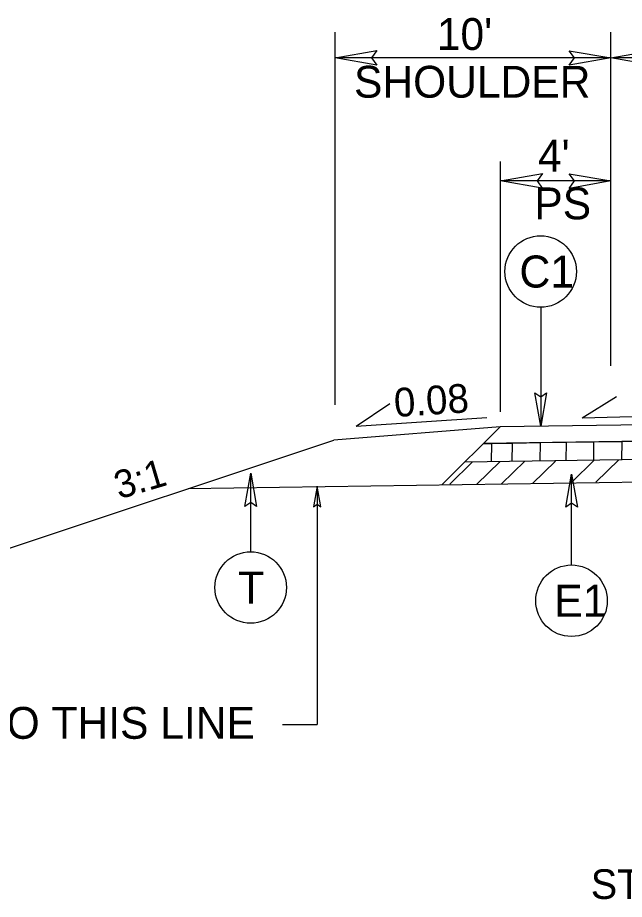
# Model space of a CAD drawing. Extents: x 2176024 to 2177225, y 75947 to 76635.
# Drawn here: x 2176290.4 to 2176312.4, y 76460.33 to 76492.28 of the extents above; entities that cross this region are included whole.
import ezdxf

# ---------------------------------------------------------------- set-up
doc = ezdxf.new("R2010")
doc.units = 0
for name, color, linetype in [('Old_Level_1', 7, 'Continuous'), ('Old_Level_11', 7, 'Continuous'), ('Prop Dimension', 7, 'Continuous'), ('Typical Curb CELL', 7, 'Continuous'), ('Typical Pavement Slope CELL', 7, 'Continuous'), ('Typical Pavement Slope Information CELL', 7, 'Continuous'), ('Typical Shoulder Slope CELL', 7, 'Continuous'), ('Typical Slope Point Local CELL', 7, 'Continuous'), ('Typical Terminator CELL', 7, 'Continuous'), ('Typical Text General CELL', 7, 'Continuous'), ('Typical Text Label CELL', 7, 'Continuous')]:
    doc.layers.add(name, color=color, linetype=linetype)

msp = doc.modelspace()

# ---------------------------------------------------------------- linework, layer by layer
at = {"layer": 'Old_Level_1'}
for p, q in [((2176307.585, 76476.185), (2176307.595, 76476.856)), ((2176308.328, 76476.198), (2176308.338, 76476.867)), ((2176309.346, 76476.211), (2176309.356, 76476.883)), ((2176310.287, 76476.218), (2176310.296, 76476.897)), ((2176311.284, 76476.242), (2176311.294, 76476.911)), ((2176312.304, 76476.264), (2176312.313, 76476.927)), ((2176306.065, 76475.376), (2176306.879, 76476.174)), ((2176307.054, 76475.376), (2176307.881, 76476.186)), ((2176307.948, 76475.394), (2176308.783, 76476.213)), ((2176309.067, 76475.398), (2176309.902, 76476.217)), ((2176310.475, 76475.439), (2176311.311, 76476.258)), ((2176311.361, 76475.445), (2176312.197, 76476.263))]:
    msp.add_line(p, q, dxfattribs=at)
at = {"layer": 'Old_Level_11'}
for p, q in [((2176309.363, 76481.787), (2176309.363, 76477.484)), ((2176298.851, 76472.929), (2176298.851, 76475.771)), ((2176310.482, 76472.45), (2176310.482, 76475.746))]:
    msp.add_line(p, q, dxfattribs=at)
for points in [[(2176309.57, 76478.684), (2176309.363, 76477.484), (2176309.15, 76478.691), (2176309.363, 76478.538)], [(2176298.644, 76474.571), (2176298.851, 76475.771), (2176299.064, 76474.565), (2176298.851, 76474.718)], [(2176310.275, 76474.546), (2176310.482, 76475.746), (2176310.695, 76474.539), (2176310.482, 76474.693)]]:
    msp.add_lwpolyline(points, close=True, dxfattribs=at)
for centre in [(2176309.363, 76483.083), (2176298.851, 76471.633), (2176310.482, 76471.154)]:
    msp.add_circle(centre, 1.296, dxfattribs=at)
at = {"layer": 'Prop Dimension'}
for p, q in [((2176301.911, 76478.254), (2176301.911, 76491.752)), ((2176311.911, 76479.67), (2176311.911, 76491.752)), ((2176311.911, 76490.824), (2176301.911, 76490.824)), ((2176323.911, 76490.824), (2176312.017, 76490.824)), ((2176307.911, 76477.998), (2176307.911, 76487.074)), ((2176311.911, 76486.364), (2176307.911, 76486.364)), ((2176301.265, 76475.31), (2176301.265, 76466.674)), ((2176300.004, 76466.674), (2176301.265, 76466.674))]:
    msp.add_line(p, q, dxfattribs=at)
at = {"layer": 'Typical Curb CELL'}
msp.add_line((2176296.587, 76475.215), (2176316.991, 76475.518), dxfattribs=at)
at = {"layer": 'Typical Pavement Slope CELL'}
for p, q in [((2176307.898, 76477.456), (2176305.781, 76475.352)), ((2176316.991, 76476.996), (2176307.29, 76476.852)), ((2176316.979, 76476.325), (2176306.605, 76476.17))]:
    msp.add_line(p, q, dxfattribs=at)
at = {"layer": 'Typical Pavement Slope Information CELL'}
for p, q in [((2176310.861, 76477.787), (2176312.117, 76478.556)), ((2176302.67, 76477.477), (2176303.895, 76478.296)), ((2176310.861, 76477.787), (2176318.366, 76477.982)), ((2176302.67, 76477.477), (2176307.416, 76477.79))]:
    msp.add_line(p, q, dxfattribs=at)
at = {"layer": 'Typical Shoulder Slope CELL'}
for p in [(2176307.898, 76477.456), (2176289.004, 76472.687)]:
    msp.add_line(p, (2176301.863, 76476.973), dxfattribs=at)
at = {"layer": 'Typical Slope Point Local CELL'}
for p, q in [((2176326.441, 76477.731), (2176307.898, 76477.456)), ((2176316.991, 76477.591), (2176307.898, 76477.456)), ((2176307.898, 76477.456), (2176307.29, 76476.852))]:
    msp.add_line(p, q, dxfattribs=at)
for points in [[(2176308.338, 76476.867), (2176309.356, 76476.883), (2176310.296, 76476.897), (2176311.294, 76476.911), (2176312.313, 76476.927), (2176313.254, 76476.941), (2176314.251, 76476.955), (2176315.284, 76476.971), (2176316.224, 76476.985), (2176316.991, 76476.996)], [(2176307.29, 76476.852), (2176307.595, 76476.856), (2176308.338, 76476.867)]]:
    msp.add_lwpolyline(points, dxfattribs=at)
at = {"layer": 'Typical Terminator CELL'}
for points in [[(2176303.42, 76490.564), (2176301.911, 76490.824), (2176303.429, 76491.093), (2176303.236, 76490.824)], [(2176310.401, 76491.084), (2176311.911, 76490.824), (2176310.393, 76490.556), (2176310.586, 76490.824)], [(2176313.42, 76490.564), (2176311.911, 76490.824), (2176313.429, 76491.093), (2176313.236, 76490.824)], [(2176309.42, 76486.104), (2176307.911, 76486.364), (2176309.429, 76486.632), (2176309.236, 76486.364)], [(2176310.401, 76486.624), (2176311.911, 76486.364), (2176310.393, 76486.096), (2176310.586, 76486.364)], [(2176301.395, 76474.555), (2176301.265, 76475.31), (2176301.131, 76474.551), (2176301.265, 76474.647)]]:
    msp.add_lwpolyline(points, close=True, dxfattribs=at)

# ---------------------------------------------------------------- texts
at = {"layer": 'Old_Level_11'}
for s, rotation, p in [('C1', 0.0003, (2176308.594, 76482.503)), ('T', 359.9997, (2176298.394, 76471.053)), ('E1', 0.0003, (2176309.854, 76470.574))]:
    msp.add_text(s, height=1.16, rotation=rotation, dxfattribs=at).set_placement(p)
at = {"layer": 'Typical Pavement Slope Information CELL'}
msp.add_text('0.08', height=1.0429, rotation=3.7801, dxfattribs=at).set_placement((2176304.08, 76477.807))
at = {"layer": 'Typical Slope Point Local CELL'}
msp.add_text('3:1', height=1.0064, rotation=16.4649, dxfattribs=at).set_placement((2176294.081, 76474.826))
at = {"layer": 'Typical Text General CELL'}
for s, height, p in [("10' ", 1.1533, (2176305.598, 76491.113)), ('SHOULDER', 1.1533, (2176302.597, 76489.383)), ("4' ", 1.1533, (2176309.263, 76486.705)), ('PS', 1.1533, (2176309.134, 76484.975)), ('GRADE TO THIS LINE', 1.15334, (2176283.149, 76466.151))]:
    msp.add_text(s, height=height, dxfattribs=at).set_placement(p)
at = {"layer": 'Typical Text Label CELL'}
msp.add_text('STA. 10+54.13 -Y1- TO STA. 15+00.00 -Y1-', height=1.0742, dxfattribs=at).set_placement((2176311.179, 76460.348))

doc.saveas('drawing.dxf')
